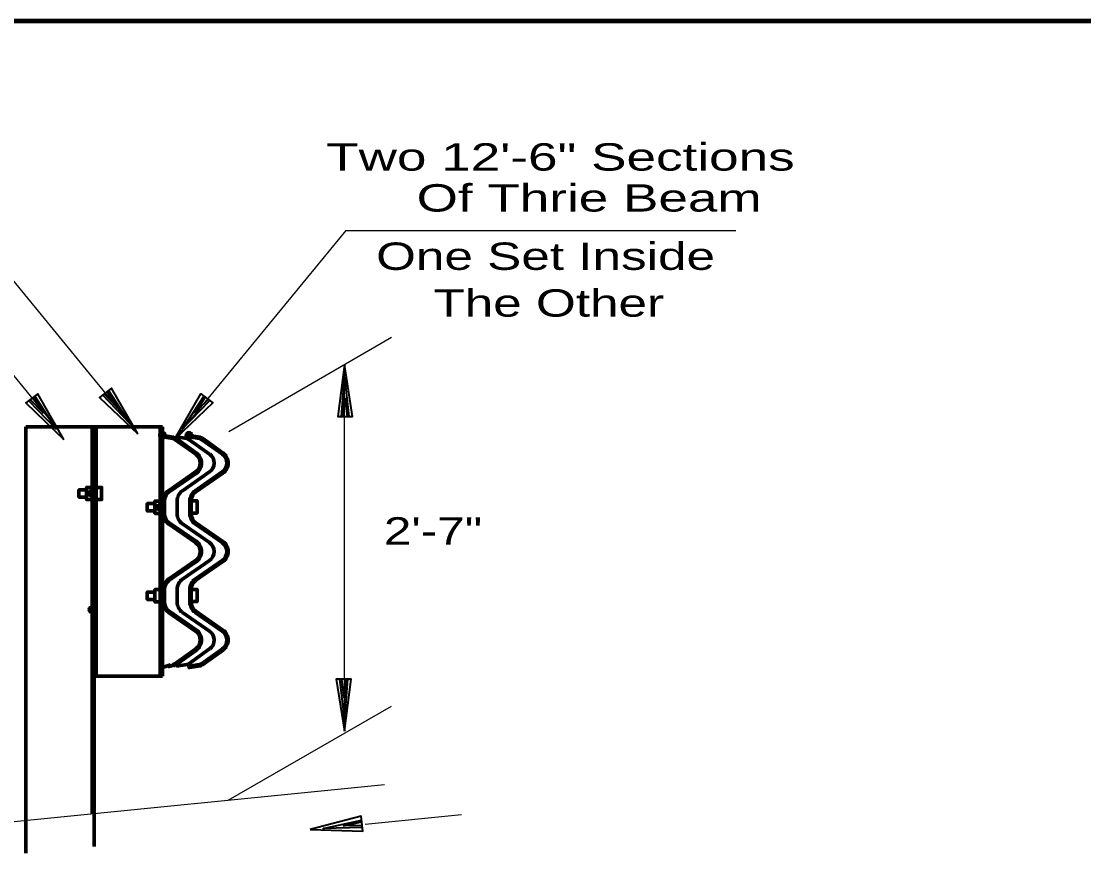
# Model space of a CAD drawing. Extents: x 856.9 to 891.7, y -2278.5 to -2254.7.
# Drawn here: x 872.81 to 877.803, y -2260.071 to -2256.163 of the extents above; entities that cross this region are included whole.
import ezdxf

# ---------------------------------------------------------------- set-up
doc = ezdxf.new("R2010")
doc.units = 0
doc.header["$LTSCALE"] = 0.051
doc.header["$PDMODE"] = 32
doc.header["$PDSIZE"] = 0.0255
doc.linetypes.add('MEDIUM_DASHED', pattern=[4.5, 3, -1.5])
doc.layers.add('1', color=7, linetype='Continuous', lineweight=70)
doc.layers.add('3', color=7, linetype='Continuous', lineweight=40)

msp = doc.modelspace()

# ---------------------------------------------------------------- linework, layer by layer
at = {"layer": '1', "lineweight": 25}
for p, q in [((872.18025, -2257.10383), (872.97158, -2258.06958)), ((872.54325, -2257.10383), (873.33458, -2258.06958)), ((874.33483, -2257.146), (873.5435, -2258.11175)), ((874.33483, -2257.146), (876.16808, -2257.146)), ((873.78533, -2258.09067), (874.55092, -2257.64858)), ((874.32892, -2259.50008), (874.32892, -2257.77692)), ((873.78333, -2259.82433), (874.54975, -2259.38225)), ((874.51683, -2259.75225), (871.78975, -2260.02467)), ((874.42708, -2259.93667), (874.879, -2259.89133))]:
    msp.add_line(p, q, dxfattribs=at)
at = {"layer": '1'}
for p, q in [((872.83242, -2258.06908), (872.83242, -2259.9205)), ((873.47358, -2258.06908), (872.83242, -2258.06908)), ((873.14283, -2258.06908), (873.14283, -2259.88983)), ((873.1525, -2258.06908), (873.1525, -2259.242)), ((873.16308, -2258.06908), (873.16308, -2259.242)), ((873.463, -2258.06908), (873.463, -2259.242)), ((873.47358, -2258.06908), (873.47358, -2259.242)), ((873.47442, -2258.10958), (873.52525, -2258.11875)), ((873.47492, -2258.11617), (873.48675, -2258.11225)), ((873.492, -2258.11942), (873.50433, -2258.11492)), ((873.50883, -2258.122), (873.52142, -2258.11825)), ((873.539, -2258.11617), (873.59017, -2258.12467)), ((873.59925, -2258.10958), (873.65042, -2258.11875)), ((873.59925, -2258.11617), (873.61175, -2258.11225)), ((873.617, -2258.11942), (873.62875, -2258.11492)), ((873.63408, -2258.122), (873.64642, -2258.11825)), ((873.526, -2258.12533), (873.53442, -2258.12275)), ((873.53242, -2258.12858), (873.63025, -2258.19808)), ((873.53567, -2258.13058), (873.54292, -2258.12858)), ((873.63408, -2258.19283), (873.53633, -2258.12333)), ((873.54425, -2258.13633), (873.5515, -2258.1345)), ((873.54825, -2258.139), (873.5515, -2258.1345)), ((873.58817, -2258.16792), (873.59142, -2258.16333)), ((873.59083, -2258.16467), (873.59275, -2258.16408)), ((873.59408, -2258.17183), (873.60125, -2258.16992)), ((873.59792, -2258.12858), (873.69567, -2258.19808)), ((873.65108, -2258.12533), (873.65958, -2258.12275)), ((873.65758, -2258.12858), (873.75525, -2258.19808)), ((873.66092, -2258.13058), (873.66808, -2258.12858)), ((873.75842, -2258.19283), (873.6615, -2258.12333)), ((873.66942, -2258.13633), (873.67658, -2258.1345)), ((873.67267, -2258.139), (873.67658, -2258.1345)), ((873.71317, -2258.16792), (873.71667, -2258.16333)), ((873.71592, -2258.16467), (873.71775, -2258.16408)), ((873.71917, -2258.17183), (873.7265, -2258.16992)), ((873.60192, -2258.17783), (873.609, -2258.17575)), ((873.6105, -2258.18358), (873.61775, -2258.18175)), ((873.619, -2258.18942), (873.62617, -2258.1875)), ((873.62683, -2258.19533), (873.63408, -2258.1935)), ((873.63467, -2258.20192), (873.64125, -2258.19933)), ((873.64125, -2258.20842), (873.64708, -2258.20658)), ((873.64592, -2258.21558), (873.65167, -2258.21367)), ((873.64908, -2258.22292), (873.655, -2258.22092)), ((873.727, -2258.17783), (873.73417, -2258.17575)), ((873.73567, -2258.18358), (873.74275, -2258.18175)), ((873.74408, -2258.18942), (873.75125, -2258.1875)), ((873.752, -2258.19533), (873.75917, -2258.1935)), ((873.75983, -2258.20192), (873.76633, -2258.19933)), ((873.76633, -2258.20842), (873.77217, -2258.20658)), ((873.77092, -2258.21558), (873.77625, -2258.21367)), ((873.77425, -2258.22292), (873.77933, -2258.22092)), ((873.64325, -2258.268), (873.65167, -2258.26492)), ((873.64842, -2258.25767), (873.65558, -2258.255)), ((873.65108, -2258.23075), (873.657, -2258.22883)), ((873.65108, -2258.24783), (873.65758, -2258.24583)), ((873.65167, -2258.23933), (873.65758, -2258.23742)), ((873.76833, -2258.268), (873.77667, -2258.26492)), ((873.7735, -2258.25767), (873.78075, -2258.255)), ((873.77625, -2258.23075), (873.78208, -2258.22883)), ((873.77625, -2258.24783), (873.78208, -2258.24583)), ((873.77667, -2258.23933), (873.78275, -2258.23742)), ((873.6295, -2258.28108), (873.50233, -2258.36967)), ((873.50575, -2258.37492), (873.63333, -2258.28642)), ((873.69483, -2258.28108), (873.56775, -2258.36967)), ((873.58492, -2258.31267), (873.60458, -2258.30608)), ((873.58817, -2258.31008), (873.59208, -2258.31525)), ((873.59675, -2258.30483), (873.61633, -2258.29825)), ((873.6085, -2258.29633), (873.62808, -2258.28983)), ((873.61967, -2258.28833), (873.63858, -2258.28258)), ((873.7545, -2258.28108), (873.6275, -2258.36967)), ((873.63083, -2258.37492), (873.75783, -2258.28642)), ((873.63142, -2258.28058), (873.6445, -2258.276)), ((873.71008, -2258.31267), (873.72967, -2258.30608)), ((873.71317, -2258.31008), (873.71667, -2258.31525)), ((873.72175, -2258.30483), (873.74133, -2258.29825)), ((873.733, -2258.29633), (873.75325, -2258.28983)), ((873.74483, -2258.28833), (873.76375, -2258.28258)), ((873.7565, -2258.28058), (873.76967, -2258.276)), ((873.503, -2258.369), (873.52333, -2258.36325)), ((873.51483, -2258.36125), (873.53442, -2258.3545)), ((873.5265, -2258.35325), (873.54625, -2258.34667)), ((873.53833, -2258.34467), (873.54958, -2258.34142)), ((873.54758, -2258.33817), (873.5515, -2258.34342)), ((873.62808, -2258.369), (873.64783, -2258.36325)), ((873.63992, -2258.36125), (873.65958, -2258.3545)), ((873.65167, -2258.35325), (873.67125, -2258.34667)), ((873.66292, -2258.34467), (873.67458, -2258.34142)), ((873.67267, -2258.33817), (873.67583, -2258.34342)), ((873.4775, -2258.41617), (873.48408, -2258.414)), ((873.4775, -2258.41675), (873.4775, -2258.47842)), ((873.47875, -2258.40758), (873.48525, -2258.40492)), ((873.48083, -2258.39775), (873.48867, -2258.39592)), ((873.48408, -2258.47842), (873.48408, -2258.41675)), ((873.48525, -2258.38792), (873.49517, -2258.38467)), ((873.48925, -2258.38217), (873.50117, -2258.37883)), ((873.49467, -2258.37617), (873.5115, -2258.37083)), ((873.54292, -2258.41675), (873.54292, -2258.47842)), ((873.6025, -2258.41617), (873.609, -2258.414)), ((873.6025, -2258.41675), (873.6025, -2258.47842)), ((873.60317, -2258.40758), (873.60975, -2258.40492)), ((873.60592, -2258.39775), (873.61383, -2258.39592)), ((873.6085, -2258.47842), (873.6085, -2258.41675)), ((873.6105, -2258.38792), (873.62033, -2258.38467)), ((873.61433, -2258.38217), (873.62617, -2258.37883)), ((873.61967, -2258.37617), (873.63683, -2258.37083)), ((873.4775, -2258.42475), (873.48408, -2258.42283)), ((873.4775, -2258.42733), (873.48408, -2258.42733)), ((873.4775, -2258.46783), (873.48408, -2258.46783)), ((873.6025, -2258.42475), (873.6085, -2258.42283)), ((873.6025, -2258.42733), (873.6085, -2258.42733)), ((873.6025, -2258.46783), (873.6085, -2258.46783)), ((873.4775, -2258.47633), (873.48408, -2258.47442)), ((873.47808, -2258.48492), (873.48408, -2258.483)), ((873.4795, -2258.49275), (873.48525, -2258.4915)), ((873.48275, -2258.50067), (873.488, -2258.49867)), ((873.48608, -2258.50792), (873.492, -2258.50658)), ((873.49125, -2258.51492), (873.49792, -2258.513)), ((873.49792, -2258.52158), (873.50433, -2258.51967)), ((873.63333, -2258.60867), (873.50575, -2258.52017)), ((873.6025, -2258.47633), (873.6085, -2258.47442)), ((873.60317, -2258.48492), (873.609, -2258.483)), ((873.60458, -2258.49275), (873.6105, -2258.4915)), ((873.60708, -2258.50067), (873.61317, -2258.49867)), ((873.61108, -2258.50792), (873.617, -2258.50658)), ((873.61633, -2258.51492), (873.62225, -2258.513)), ((873.623, -2258.52158), (873.6295, -2258.51967)), ((873.75783, -2258.60867), (873.63083, -2258.52017)), ((873.50233, -2258.52558), (873.6295, -2258.61342)), ((873.50575, -2258.52742), (873.51292, -2258.52558)), ((873.51425, -2258.53325), (873.52142, -2258.53133)), ((873.52258, -2258.53925), (873.52983, -2258.5365)), ((873.53125, -2258.54508), (873.53833, -2258.54242)), ((873.53967, -2258.55108), (873.547, -2258.54842)), ((873.54758, -2258.557), (873.5515, -2258.55183)), ((873.56775, -2258.52558), (873.69483, -2258.61342)), ((873.6275, -2258.52558), (873.7545, -2258.61342)), ((873.63083, -2258.52742), (873.638, -2258.52558)), ((873.63925, -2258.53325), (873.64642, -2258.53133)), ((873.64783, -2258.53925), (873.655, -2258.5365)), ((873.65633, -2258.54508), (873.6635, -2258.54242)), ((873.66475, -2258.55108), (873.672, -2258.54842)), ((873.67267, -2258.557), (873.67583, -2258.55183)), ((873.58817, -2258.58517), (873.59208, -2258.57983)), ((873.59017, -2258.58642), (873.59742, -2258.58383)), ((873.59867, -2258.59233), (873.60592, -2258.58967)), ((873.60708, -2258.59825), (873.61433, -2258.5955)), ((873.61575, -2258.6035), (873.623, -2258.6015)), ((873.62425, -2258.60925), (873.63142, -2258.60733)), ((873.63275, -2258.61533), (873.63925, -2258.61342)), ((873.63925, -2258.62183), (873.64517, -2258.61992)), ((873.71317, -2258.58517), (873.71667, -2258.57983)), ((873.71517, -2258.58642), (873.7225, -2258.58383)), ((873.72383, -2258.59233), (873.73083, -2258.58967)), ((873.73225, -2258.59825), (873.73942, -2258.5955)), ((873.74075, -2258.6035), (873.748, -2258.6015)), ((873.74925, -2258.60925), (873.7565, -2258.60733)), ((873.75717, -2258.61533), (873.76433, -2258.61342)), ((873.76433, -2258.62183), (873.77017, -2258.61992)), ((873.6445, -2258.629), (873.65042, -2258.62708)), ((873.64783, -2258.63625), (873.65367, -2258.63425)), ((873.64983, -2258.67025), (873.65633, -2258.66825)), ((873.65042, -2258.64408), (873.65633, -2258.642)), ((873.65108, -2258.66108), (873.65758, -2258.65908)), ((873.65167, -2258.65267), (873.65758, -2258.65075)), ((873.76908, -2258.629), (873.77483, -2258.62708)), ((873.77292, -2258.63625), (873.77875, -2258.63425)), ((873.77425, -2258.67025), (873.78133, -2258.66825)), ((873.77558, -2258.64408), (873.78133, -2258.642)), ((873.77625, -2258.66108), (873.78275, -2258.65908)), ((873.77667, -2258.65267), (873.78275, -2258.65075)), ((873.6295, -2258.69783), (873.50233, -2258.7855)), ((873.50575, -2258.79058), (873.63333, -2258.70242)), ((873.69483, -2258.69783), (873.56775, -2258.7855)), ((873.59275, -2258.72342), (873.61317, -2258.71683)), ((873.60458, -2258.71467), (873.625, -2258.70817)), ((873.61633, -2258.70692), (873.636, -2258.70042)), ((873.7545, -2258.69783), (873.6275, -2258.7855)), ((873.62808, -2258.69908), (873.64325, -2258.69383)), ((873.63083, -2258.79058), (873.75783, -2258.70242)), ((873.63683, -2258.69175), (873.64783, -2258.688)), ((873.64517, -2258.68017), (873.653, -2258.67742)), ((873.71775, -2258.72342), (873.73808, -2258.71683)), ((873.72967, -2258.71467), (873.74925, -2258.70817)), ((873.74133, -2258.70692), (873.76108, -2258.70042)), ((873.75267, -2258.69908), (873.7675, -2258.69383)), ((873.76183, -2258.69175), (873.77217, -2258.688)), ((873.77017, -2258.68017), (873.77817, -2258.67742)), ((873.52258, -2258.77183), (873.54292, -2258.76517)), ((873.53442, -2258.76325), (873.55083, -2258.758)), ((873.54758, -2258.75408), (873.5515, -2258.75933)), ((873.58817, -2258.72592), (873.59208, -2258.731)), ((873.59017, -2258.7285), (873.60125, -2258.7245)), ((873.64783, -2258.77183), (873.66808, -2258.76517)), ((873.65958, -2258.76325), (873.67525, -2258.758)), ((873.67267, -2258.75408), (873.67583, -2258.75933)), ((873.71317, -2258.72592), (873.71667, -2258.731)), ((873.71517, -2258.7285), (873.7265, -2258.7245)), ((873.4795, -2258.82033), (873.48608, -2258.81833)), ((873.48208, -2258.81042), (873.48983, -2258.80775)), ((873.488, -2258.79992), (873.49917, -2258.79658)), ((873.49258, -2258.79408), (873.50775, -2258.7895)), ((873.49975, -2258.7875), (873.51942, -2258.7815)), ((873.51092, -2258.77967), (873.53125, -2258.77308)), ((873.60392, -2258.82033), (873.61108, -2258.81833)), ((873.60708, -2258.81042), (873.615, -2258.80775)), ((873.61317, -2258.79992), (873.62358, -2258.79658)), ((873.61775, -2258.79408), (873.63275, -2258.7895)), ((873.625, -2258.7875), (873.6445, -2258.7815)), ((873.636, -2258.77967), (873.65633, -2258.77308)), ((873.4775, -2258.83267), (873.4775, -2258.89425)), ((873.4775, -2258.83792), (873.48408, -2258.836)), ((873.4775, -2258.84325), (873.48408, -2258.84325)), ((873.47808, -2258.8295), (873.48408, -2258.82742)), ((873.48408, -2258.89425), (873.48408, -2258.83267)), ((873.54292, -2258.83267), (873.54292, -2258.89425)), ((873.6025, -2258.8295), (873.609, -2258.82742)), ((873.6025, -2258.83267), (873.6025, -2258.89425)), ((873.6025, -2258.83792), (873.6085, -2258.836)), ((873.6025, -2258.84325), (873.6085, -2258.84325)), ((873.6085, -2258.89425), (873.6085, -2258.83267)), ((873.4775, -2258.88383), (873.48408, -2258.88383)), ((873.4775, -2258.88967), (873.48408, -2258.88775)), ((873.47808, -2258.89825), (873.48408, -2258.89617)), ((873.47875, -2258.906), (873.48475, -2258.90483)), ((873.4815, -2258.914), (873.48733, -2258.9125)), ((873.48475, -2258.92167), (873.49067, -2258.91983)), ((873.6025, -2258.88383), (873.6085, -2258.88383)), ((873.6025, -2258.88967), (873.6085, -2258.88775)), ((873.6025, -2258.89825), (873.609, -2258.89617)), ((873.60392, -2258.906), (873.60975, -2258.90483)), ((873.60658, -2258.914), (873.61233, -2258.9125)), ((873.60975, -2258.92167), (873.61575, -2258.91983)), ((873.48925, -2258.92892), (873.49583, -2258.927)), ((873.49517, -2258.93542), (873.50167, -2258.9335)), ((873.50233, -2258.94142), (873.6295, -2259.02917)), ((873.503, -2258.94142), (873.51025, -2258.9395)), ((873.63333, -2259.02475), (873.50575, -2258.93608)), ((873.5115, -2258.94733), (873.51883, -2258.94542)), ((873.52, -2258.95325), (873.52725, -2258.95125)), ((873.52858, -2258.95917), (873.53567, -2258.95725)), ((873.53633, -2258.96492), (873.54358, -2258.96242)), ((873.545, -2258.97092), (873.55025, -2258.96892)), ((873.54758, -2258.97283), (873.5515, -2258.96758)), ((873.56775, -2258.94142), (873.69483, -2259.02917)), ((873.61433, -2258.92892), (873.62033, -2258.927)), ((873.62033, -2258.93542), (873.62683, -2258.9335)), ((873.6275, -2258.94142), (873.7545, -2259.02917)), ((873.62808, -2258.94142), (873.63525, -2258.9395)), ((873.75783, -2259.02475), (873.63083, -2258.93608)), ((873.63683, -2258.94733), (873.644, -2258.94542)), ((873.6445, -2258.95325), (873.65167, -2258.95125)), ((873.653, -2258.95917), (873.66025, -2258.95725)), ((873.6615, -2258.96492), (873.66858, -2258.96242)), ((873.67008, -2258.97092), (873.67525, -2258.96892)), ((873.67267, -2258.97283), (873.67583, -2258.96758)), ((873.58817, -2259.001), (873.59208, -2258.99575)), ((873.5895, -2258.99967), (873.59475, -2258.99775)), ((873.59592, -2259.00617), (873.60317, -2259.00375)), ((873.60458, -2259.01217), (873.61175, -2259.00942)), ((873.61317, -2259.01808), (873.62033, -2259.01533)), ((873.71317, -2259.001), (873.71667, -2258.99575)), ((873.71467, -2258.99967), (873.71983, -2258.99775)), ((873.72117, -2259.00617), (873.72833, -2259.00375)), ((873.729, -2259.01217), (873.73617, -2259.00942)), ((873.73758, -2259.01808), (873.74483, -2259.01533)), ((873.62092, -2259.024), (873.62808, -2259.02125)), ((873.6295, -2259.02917), (873.63683, -2259.02717)), ((873.63733, -2259.03558), (873.64325, -2259.03392)), ((873.6425, -2259.04225), (873.64842, -2259.04033)), ((873.64708, -2259.0495), (873.65233, -2259.04742)), ((873.64983, -2259.05733), (873.65558, -2259.05533)), ((873.65108, -2259.06517), (873.657, -2259.06325)), ((873.74608, -2259.024), (873.75325, -2259.02125)), ((873.7545, -2259.02917), (873.76183, -2259.02717)), ((873.76183, -2259.03558), (873.76833, -2259.03392)), ((873.7675, -2259.04225), (873.7735, -2259.04033)), ((873.77158, -2259.0495), (873.77742, -2259.04742)), ((873.77483, -2259.05733), (873.78075, -2259.05533)), ((873.77625, -2259.06517), (873.78208, -2259.06325)), ((873.63025, -2259.113), (873.53242, -2259.1825)), ((873.53633, -2259.18758), (873.63408, -2259.11825)), ((873.69567, -2259.113), (873.59792, -2259.1825)), ((873.61383, -2259.12475), (873.63275, -2259.11892)), ((873.625, -2259.11692), (873.64125, -2259.11167)), ((873.63467, -2259.10975), (873.64642, -2259.10583)), ((873.6405, -2259.10317), (873.64983, -2259.10058)), ((873.64708, -2259.09275), (873.65433, -2259.09008)), ((873.65042, -2259.08292), (873.657, -2259.08092)), ((873.65167, -2259.07375), (873.65758, -2259.07175)), ((873.75525, -2259.113), (873.65758, -2259.1825)), ((873.6615, -2259.18758), (873.75842, -2259.11825)), ((873.73808, -2259.12475), (873.75783, -2259.11892)), ((873.74925, -2259.11692), (873.76633, -2259.11167)), ((873.75983, -2259.10975), (873.77158, -2259.10583)), ((873.76558, -2259.10317), (873.77483, -2259.10058)), ((873.77217, -2259.09275), (873.77933, -2259.09008)), ((873.77558, -2259.08292), (873.78208, -2259.08092)), ((873.77667, -2259.07375), (873.78275, -2259.07175)), ((873.58817, -2259.14325), (873.59142, -2259.14775)), ((873.59017, -2259.14583), (873.59925, -2259.14267)), ((873.59142, -2259.14117), (873.6105, -2259.13458)), ((873.6025, -2259.13267), (873.62158, -2259.12675)), ((873.71317, -2259.14325), (873.71667, -2259.14775)), ((873.71517, -2259.14583), (873.72425, -2259.14267)), ((873.71667, -2259.14117), (873.73567, -2259.13458)), ((873.72767, -2259.13267), (873.74675, -2259.12675)), ((873.47442, -2259.2), (873.51092, -2259.18833)), ((873.49858, -2259.19675), (873.54425, -2259.18175)), ((873.51292, -2259.19417), (873.53833, -2259.18567)), ((873.53567, -2259.18042), (873.55083, -2259.176)), ((873.59017, -2259.18633), (873.539, -2259.19483)), ((873.54158, -2259.17642), (873.54958, -2259.17392)), ((873.54825, -2259.172), (873.5515, -2259.17642)), ((873.64983, -2259.18633), (873.59792, -2259.19483)), ((873.59867, -2259.19875), (873.62158, -2259.19083)), ((873.59867, -2259.19625), (873.60708, -2259.19358)), ((873.59925, -2259.2), (873.636, -2259.18833)), ((873.609, -2259.19942), (873.67458, -2259.17783)), ((873.62358, -2259.19675), (873.66858, -2259.18175)), ((873.638, -2259.19417), (873.6635, -2259.18567)), ((873.66092, -2259.18042), (873.67583, -2259.176)), ((873.66617, -2259.17642), (873.67458, -2259.17392)), ((873.67267, -2259.172), (873.67658, -2259.17642)), ((873.47358, -2259.242), (873.1525, -2259.242)), ((873.1525, -2259.242), (873.1525, -2259.8885))]:
    msp.add_line(p, q, dxfattribs=at)
at = {"layer": '1', "lineweight": 13}
for p, q in [((873.52458, -2259.18633), (873.47358, -2259.19483)), ((873.47358, -2259.19875), (873.49642, -2259.19083)), ((873.47358, -2259.19625), (873.48208, -2259.19358)), ((873.48408, -2259.19942), (873.54958, -2259.17783))]:
    msp.add_line(p, q, dxfattribs=at)
at = {"layer": '1', "linetype": 'MEDIUM_DASHED'}
for p, q in [((873.1525, -2259.8885), (873.1525, -2262.32625)), ((872.83242, -2259.9205), (872.83242, -2262.32625))]:
    msp.add_line(p, q, dxfattribs=at)
at = {"layer": '1', "lineweight": 40}
for points in [[(874.32892, -2257.77692), (874.29758, -2258.02117), (874.3675, -2258.02117)], [(873.01033, -2258.12875), (872.88767, -2257.91467), (872.8315, -2257.95717)], [(873.3575, -2258.10242), (873.23483, -2257.88833), (873.17867, -2257.93083)], [(873.531, -2258.12875), (873.65367, -2257.91467), (873.70983, -2257.95717)], [(874.32892, -2259.50008), (874.36033, -2259.25583), (874.29025, -2259.25583)], [(874.1685, -2259.96258), (874.41483, -2259.96975), (874.40833, -2259.89975)]]:
    msp.add_lwpolyline(points, close=True, dxfattribs=at)
for points in [[(874.31517, -2258.02117), (874.32892, -2257.83775), (874.34992, -2258.02117)], [(873.22067, -2257.89917), (873.32033, -2258.05308), (873.19308, -2257.92025)], [(873.21333, -2257.90433), (873.261, -2257.97792), (873.19992, -2257.91467)], [(872.8735, -2257.9255), (872.97317, -2258.07942), (872.84592, -2257.94658)], [(872.86617, -2257.93067), (872.91383, -2258.00425), (872.85275, -2257.941)], [(873.66783, -2257.9255), (873.56817, -2258.07942), (873.69542, -2257.94658)], [(873.67517, -2257.93067), (873.6275, -2258.00425), (873.68858, -2257.941)], [(874.32375, -2258.02117), (874.33092, -2257.93408), (874.34133, -2258.02117)], [(874.34275, -2259.25583), (874.32892, -2259.43917), (874.30792, -2259.25583)], [(874.33425, -2259.25583), (874.327, -2259.34292), (874.3165, -2259.25583)], [(874.41358, -2259.95217), (874.22942, -2259.95675), (874.4095, -2259.91725)], [(874.41225, -2259.9435), (874.32508, -2259.94508), (874.41092, -2259.926)]]:
    msp.add_lwpolyline(points, dxfattribs=at)
at = {"layer": '1'}
for points in [[(873.47442, -2258.10958), (873.47358, -2258.11617), (873.52458, -2258.12467)], [(873.59925, -2258.10958), (873.59792, -2258.11617), (873.64983, -2258.12467)], [(873.11725, -2258.36575), (873.08133, -2258.36575), (873.08133, -2258.39975), (873.11725, -2258.39975)], [(873.14283, -2258.35392), (873.11725, -2258.35392), (873.11725, -2258.4115), (873.14283, -2258.4115)], [(873.16308, -2258.35392), (873.188, -2258.35392), (873.188, -2258.4115), (873.16308, -2258.4115)], [(873.463, -2258.41817), (873.43825, -2258.41817), (873.43825, -2258.47633), (873.463, -2258.47633)], [(873.61175, -2258.41675), (873.63683, -2258.41675), (873.63683, -2258.47517), (873.61175, -2258.47517)], [(873.43825, -2258.43042), (873.40225, -2258.43042), (873.40225, -2258.46467), (873.43825, -2258.46467)], [(873.43825, -2258.84642), (873.40225, -2258.84642), (873.40225, -2258.8805), (873.43825, -2258.8805)], [(873.463, -2258.83467), (873.43825, -2258.83467), (873.43825, -2258.89225), (873.463, -2258.89225)], [(873.61175, -2258.83333), (873.63683, -2258.83333), (873.63683, -2258.89108), (873.61175, -2258.89108)], [(873.59792, -2259.19483), (873.59925, -2259.20075), (873.65042, -2259.19225)]]:
    msp.add_lwpolyline(points, dxfattribs=at)
at = {"layer": '1', "lineweight": 13}
msp.add_lwpolyline([(873.47358, -2259.19483), (873.47442, -2259.20075), (873.52525, -2259.19225)], dxfattribs=at)
at = {"layer": '1'}
for centre, radius, start, end in [((873.52096, -2258.14508), 0.02652, 54.50882, 79.99842), ((873.64593, -2258.14508), 0.02652, 54.50882, 79.99842), ((873.52096, -2258.14508), 0.02046, 54.50882, 79.99842), ((873.60054, -2258.23951), 0.05115, 304.74043, 54.50779), ((873.60054, -2258.23951), 0.0572, 304.74043, 54.5106), ((873.66603, -2258.23951), 0.05115, 304.74043, 54.50779), ((873.7255, -2258.23951), 0.05115, 304.74043, 54.50779), ((873.7255, -2258.23951), 0.0572, 304.74043, 54.5106), ((873.53499, -2258.41682), 0.0572, 124.73767, 180), ((873.60048, -2258.41682), 0.0572, 124.73767, 180), ((873.65995, -2258.41682), 0.0572, 124.73767, 180), ((873.53499, -2258.41682), 0.05115, 124.73767, 180), ((873.65995, -2258.41682), 0.05115, 124.73767, 180), ((873.53499, -2258.4782), 0.0572, 180, 235.26233), ((873.53499, -2258.4782), 0.05115, 180, 235.26233), ((873.60048, -2258.4782), 0.0572, 180, 235.26233), ((873.65995, -2258.4782), 0.0572, 180, 235.26233), ((873.65995, -2258.4782), 0.05115, 180, 235.26233), ((873.60054, -2258.65551), 0.05115, 304.73767, 55.26233), ((873.60054, -2258.65551), 0.0572, 304.74043, 55.25957), ((873.66603, -2258.65551), 0.05115, 304.73767, 55.26233), ((873.7255, -2258.65551), 0.05115, 304.73767, 55.26233), ((873.7255, -2258.65551), 0.0572, 304.74043, 55.25957), ((873.53499, -2258.83282), 0.0572, 124.73767, 180), ((873.53499, -2258.83282), 0.05115, 124.73767, 180), ((873.60048, -2258.83282), 0.0572, 124.73767, 180), ((873.65995, -2258.83282), 0.0572, 124.73767, 180), ((873.65995, -2258.83282), 0.05115, 124.73767, 180), ((873.53499, -2258.8942), 0.0572, 180, 235.26233), ((873.53499, -2258.8942), 0.05115, 180, 235.26233), ((873.60048, -2258.8942), 0.0572, 180, 235.26233), ((873.65995, -2258.8942), 0.0572, 180, 235.26233), ((873.65995, -2258.8942), 0.05115, 180, 235.26233), ((873.60054, -2259.07151), 0.05115, 305.49221, 55.25957), ((873.60054, -2259.07151), 0.0572, 305.4894, 55.25957), ((873.66603, -2259.07151), 0.05115, 305.49221, 55.25957), ((873.7255, -2259.07151), 0.05115, 305.49221, 55.25957), ((873.7255, -2259.07151), 0.0572, 305.4894, 55.25957), ((873.52096, -2259.16595), 0.02046, 280.00158, 305.49118), ((873.52096, -2259.16595), 0.02652, 280.00158, 305.49118), ((873.64593, -2259.16595), 0.02652, 280.00158, 305.49118)]:
    msp.add_arc(centre, radius, start, end, dxfattribs=at)
for centre, major_axis, start_param, end_param in [((873.58646, -2258.14508), (0, -0.02046), 2.5221547, 2.9670321), ((873.64593, -2258.14508), (0, -0.02046), 2.5221547, 2.9670321), ((873.58646, -2259.16595), (0, 0.02046), 3.3161532, 3.7610306), ((873.64593, -2259.16595), (0, 0.02046), 3.3161532, 3.7610306)]:
    msp.add_ellipse(centre, major_axis=major_axis, ratio=1, start_param=start_param, end_param=end_param, dxfattribs=at)
for p in [(873.47358, -2258.10958), (873.59792, -2258.10958), (873.14283, -2258.38275), (873.463, -2258.44758), (873.14283, -2258.92825)]:
    msp.add_point(p, dxfattribs=at)
at = {"layer": '3', "lineweight": 158}
msp.add_line((891.2, -2256.16333), (858.7, -2256.16333), dxfattribs=at)

# ---------------------------------------------------------------- texts
at = {"layer": '1'}
for s, width, p in [('Two 12\'-6" Sections ', 1.45, (874.24333, -2256.86533)), ('Of Thrie Beam', 1.45, (874.66817, -2257.05775)), ('One Set Inside', 1.4, (874.47775, -2257.33183)), (' The Other', 1.4, (874.68017, -2257.55175)), ('2\'-7"', 1.35, (874.51433, -2258.62283))]:
    msp.add_text(s, height=0.1286, dxfattribs=dict(at, width=width)).set_placement(p)

doc.saveas('drawing.dxf')
